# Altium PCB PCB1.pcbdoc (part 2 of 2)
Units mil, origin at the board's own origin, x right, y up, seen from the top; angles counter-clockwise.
Board outline 3543.4 x 3543.1 mil, 4 copper layers (Top Layer, Inner1, Inner2, Bottom Layer), stack 62.5 mil thick; 107 components, 108 nets, 595 pads, 260 vias.
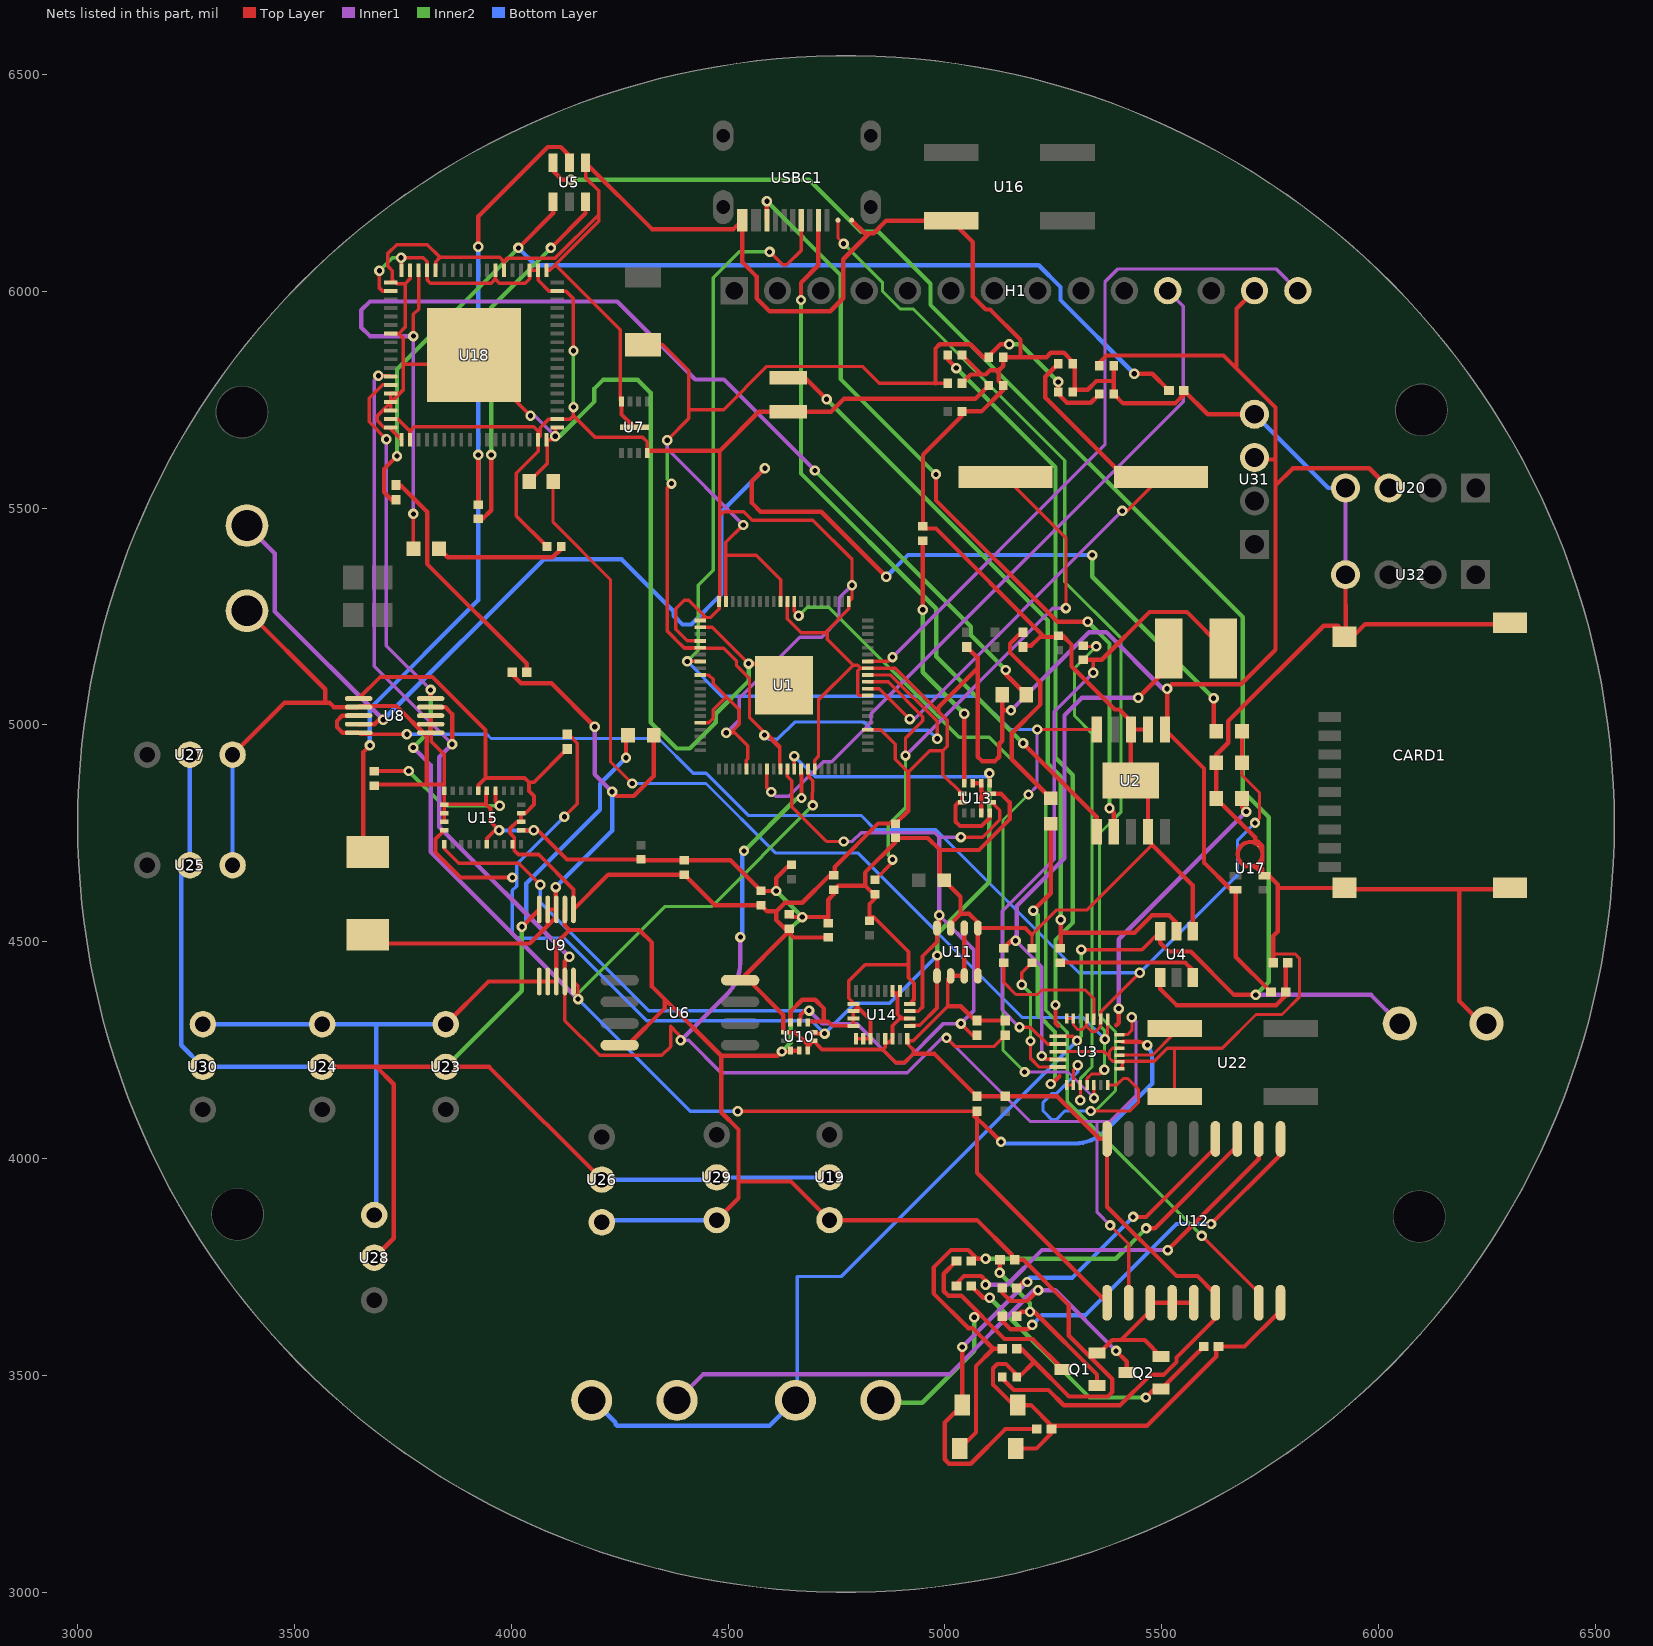
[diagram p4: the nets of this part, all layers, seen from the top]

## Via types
v1: diameter 24, hole 12, Top Layer to Bottom Layer, tented both sides, 260 vias

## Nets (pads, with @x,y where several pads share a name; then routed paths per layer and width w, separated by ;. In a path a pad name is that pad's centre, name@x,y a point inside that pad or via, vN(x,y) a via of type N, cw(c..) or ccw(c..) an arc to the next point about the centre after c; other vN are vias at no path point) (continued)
$1N198: R36.1 U1.11 U10.4 U11.5 U13.11 U14.4 U15.20 | length 2976.1
  Top Layer w7.8: U15.20@3845.1,4725 3845.1,4715 3878.8,4681.3 4016.6,4681.3 v1(4066.6,4631.3) ; U1.11@4636.6,4898.3 4636.6,4881.3 4647,4870.9 4647,4810.9 4726.6,4731.3 v1(4766.6,4731.3) ; v1(5036.6,4741.3) 5086.6,4741.3 5126.6,4781.3 5126.6,4803.2 U13.11@5108.1,4821.7
  Top Layer w8.5: U10.4@4663.7,4314.1 4666.6,4316.9 4666.6,4331.3 4676.6,4341.3 v1(4686.6,4341.3) ; U14.4@4918.7,4340 4919,4339.6 4938.3,4339.6 4948.3,4349.6 4948.3,4466.5 4981.5,4499.6 U11.5@4981.5,4531.6 ; v1(5036.6,4311.3) 5063.5,4284.4 R36.1@5073.8,4284.4
  Top Layer w9.9: U11.5@4981.5,4531.6 4986.6,4536.7 v1(4986.6,4561.3)
  Inner1 w7.8: v1(4766.6,4731.3) 4786.6,4731.3 4806.6,4751.3 4976.6,4751.3 4986.6,4741.3 v1(5036.6,4741.3)
  Inner1 w8.5: v1(4686.6,4341.3) 4716.6,4311.3 4796.6,4311.3 4886.6,4221.3 4906.6,4221.3 4996.6,4311.3 v1(5036.6,4311.3) 5066.6,4341.3 5066.6,4481.3 v1(4986.6,4561.3)
  Inner1 w9.9: v1(4986.6,4561.3) 4986.6,4741.3
  Bottom Layer w7.8: v1(4066.6,4631.3) 4066.6,4591.3 4316.6,4341.3 v1(4686.6,4341.3)
$1N204: C25.1 U15.9 | length 361.3
  Top Layer w8.9: C25.1@3683.7,4893 3684.4,4893.8 v1(3763.2,4893.8) ; U15.9@3963.2,4848 3963.2,4823.8 v1(3973.2,4813.8)
  Inner2 w8.9: v1(3763.2,4893.8) 3843.2,4813.8 v1(3973.2,4813.8)
$1N209: LED2.2 U3.1 | length 669
  Top Layer w10: v1(5203.7,4572) 5243.7,4612 LED2.2@5243.7,4772 ; v1(5243.7,4172) 5246,4172 5263.9,4189.9
  Inner2 w10: v1(5203.7,4572) 5213.7,4562 5213.7,4332 5253.7,4292 5253.7,4182 v1(5243.7,4172)
$1N210: LED2.1 R8.1 | length 491.1
  Top Layer w10: R8.1@5180,5214 5176.7,5214 5150,5187.4 5150,5167.4 5220,5097.4 5220,5047.4 5153.7,4981 5153.7,4921 LED2.1@5243.7,4831
$1N211: C17.1 U3.4 | length 1161.1
  Top Layer w7.1: v1(5312,4134.4) U3.4@5312,4169.7 ; C17.1@5318.7,5183 5320.7,5181.1 v1(5348.7,5181.1)
  Inner2 w7.1: v1(5312,4134.4) 5312,4184.4 5338.7,4211.1 5338.7,4981.1 5298.7,5021.1 5298.7,5131.1 v1(5348.7,5181.1)
$1N212: C17.2 L4.1 U3.26 | length 1460.2
  Top Layer w7.8: v1(5171.7,4303.3) 5196.7,4303.3 5236.7,4263.3 5259.9,4263.3 U3.26@5260.8,4264.2 ; v1(5341.7,5120.4) 5341.7,5150.4
  Top Layer w10: C17.2@5318.7,5150 5319.1,5150.4 5361.7,5150.4 5471.7,5260.4 5557.8,5260.4 L4.1@5641.7,5176.5
  Inner1 w7.8: v1(5171.7,4303.3) 5131.7,4343.3 5131.7,4570.4 5251.7,4690.4 5251.7,5030.4 v1(5341.7,5120.4)
$1N215: U3.12 U22.1 | length 158.8
  Top Layer w7.1: U3.12@5402.5,4238.6 5478.4,4238.6 5529.8,4290 U22.1@5529.8,4300.2
$1N219: C18.1 U3.19 | length 324.4
  Top Layer w7.1: C18.1@5135.5,4452.1 5135.5,4406.6 5163.5,4378.6 5213.5,4378.6 5223.5,4388.6 5323.5,4388.6 5343.5,4368.6 U3.19@5343.5,4321.7
$1N221: R1.1 U3.16 | length 651
  Top Layer w10: 5395.1,4307.6 5400.5,4313 5400.5,4317.4 v1(5400.5,4346) ; R1.1@5684.8,4830.3 5684.8,4810.3 v1(5694.8,4800.3)
  Inner1 w10: v1(5400.5,4346) 5400.5,4506 v1(5694.8,4800.3)
$1N224: C10.1 U3.25 U4.3 U5.3 U21.1 U33.1 | length 5744.7
  Top Layer w7.8: U3.25@5260.8,4281.9 5294.4,4281.9 v1(5304.4,4271.9) ; v1(5314.4,4481.9) 5454.3,4481.9 U4.3@5496.5,4524.2
  Top Layer w10: U5.3@4096.5,6296.5 4096.5,6277.5 4116.5,6257.5 v1(4136.5,6257.5) ; U4.3@5496.5,4524.2 5496.5,4497.5 5516.5,4477.5 5566.5,4477.5 5666.5,4377.5 v1(5716.5,4377.5)
  Inner1 w10: v1(5716.5,4377.5) 5982.7,4377.5 C10.1@6048.7,4311.5
  Inner2 w7.8: v1(5304.4,4271.9) 5314.4,4281.9 v1(5314.4,4481.9)
  Inner2 w10: v1(4136.5,6257.5) 4686.5,6257.5 4806.5,6137.5 4846.5,6137.5 4966.5,6017.5 4966.5,5968.7 5686.5,5248.7 5686.5,4847.5 5746.5,4787.5 5746.5,4407.5 v1(5716.5,4377.5)
  Bottom Layer w7.8: U21.1@4655.1,3442.4 4655.1,3443.7 4659.2,3447.8 4659.2,3727.8 ; 4660.6,3728.1 4760.5,3728.1 v1(5304.4,4271.9)
  Bottom Layer w10: U33.1@4199.4,3431.9 4238.3,3393 ; 4238.23,3392.93 cw(c4231.3,3386) 4241.1,3386 ; 4243.8,3383.7 4595.1,3383.7 U21.1@4655.1,3443.7
$1N225: C19.1 U3.29 | length 309.8
  Top Layer w7.8: v1(5177.2,4401.1) 5177.2,4428.8 C19.1@5200.5,4452.1 ; v1(5197.2,4271.1) 5197.2,4231.1 5217.2,4211.1 U3.29@5259.8,4211.1
  Inner2 w7.8: v1(5177.2,4401.1) 5197.2,4381.1 v1(5197.2,4271.1)
$1N229: C18.2 L4.2 U3.28 | length 1262.7
  Top Layer w7.8: v1(5222.9,4236.6) 5230.8,4228.8 U3.28@5260.8,4228.8
  Top Layer w10: C18.2@5135.5,4485.2 5152.9,4502.6 v1(5162.9,4502.6) ; v1(5445.7,5062.6) 5515.7,5132.6 L4.2@5515.7,5176.5
  Inner1 w7.8: v1(5162.9,4502.6) 5222.9,4442.6 v1(5222.9,4236.6)
  Inner1 w10: v1(5162.9,4502.6) 5162.9,4512.6 5165.7,4515.4 5165.7,4582.6 5275.7,4692.6 5275.7,5022.6 5315.7,5062.6 v1(5445.7,5062.6)
$1N233: U2.7 USBC1.B5 | length 1870.9
  Top Layer w10: v1(4589.3,6207.9) 4589.3,6164.6 USBC1.B5@4589.8,6164.1 ; v1(4979.3,5577.9) 4979.3,5517.9 5259.3,5237.9 v1(5329.3,5237.9) ; v1(5379.3,4807.9) 5389.3,4797.9 U2.7@5389.3,4753.4
  Inner2 w10: v1(4589.3,6207.9) 4759.3,6037.9 4759.3,5797.9 v1(4979.3,5577.9) ; v1(5329.3,5237.9) 5379.3,5187.9 v1(5379.3,4807.9)
$1N234: U2.6 USBC1.A5 | length 1709.8
  Top Layer w10: v1(4667.9,5980) 4667.9,6020 4707.9,6060 USBC1.A5@4707.9,6164.1 ; v1(5180,4957.9) 5350,4787.9 U2.6@5350,4753.4
  Inner2 w10: v1(4667.9,5980) 4667.9,5580 4980,5267.9 4980,5157.9 v1(5180,4957.9)
$1N235: U1.67 U2.5 U3.6 USBC1.A6 | length 3331
  Top Layer w7.1: v1(5343.6,4139.6) U3.6@5343.6,4169.6
  Top Layer w7.8: v1(4405.5,5146.6) U1.67@4435.5,5146.6 ; v1(4595.5,6091) 4625.5,6061 4635.5,6061 4668.5,6094.1 USBC1.A6@4668.5,6164.1 ; v1(5212.5,4989.6) U2.5@5350,4989.6
  Inner1 w7.1: v1(5183.6,4199.6) 5283.6,4199.6 v1(5343.6,4139.6) ; v1(5192.5,4839.6) 5212.5,4859.6 v1(5212.5,4989.6)
  Inner2 w7.1: v1(5183.6,4199.6) 5133.6,4249.6 5133.6,4780.7 v1(5192.5,4839.6)
  Inner2 w7.8: v1(4405.5,5146.6) 4431.2,5172.3 4431.2,5322.3 4465.5,5356.6 4465.5,6031 4525.5,6091 v1(4595.5,6091)
  Bottom Layer w7.8: v1(4405.5,5146.6) 4485.5,5066.6 5073,5066.6 5150,4989.6 v1(5212.5,4989.6)
$1N241: C21.1 U5.6 | length 839.5
  Top Layer w10: C21.1@3923.7,5475 3933.7,5475 3953.7,5495 v1(3953.7,5622.7) ; v1(4091.1,6100.1) 4171.1,6180.1 U5.6@4171.1,6206.2
  Inner2 w10: v1(3953.7,5622.7) 3953.7,5962.7 v1(4091.1,6100.1)
$1N244: C21.2 L3.1 U5.2 | length 1995.2
  Top Layer w10: L3.1@3668.7,4707 3658.7,4717 3658.7,4937.8 v1(3673.7,4952.8) ; C21.2@3923.7,5508 v1(3923.7,5622.8) ; v1(3923.7,6102.8) 3923.7,6172.8 4083.7,6332.8 4113.7,6332.8 4133.7,6312.8 U5.2@4133.7,6296.7
  Bottom Layer w10: v1(3673.7,4952.8) 3673.7,5037.9 3923.7,5287.9 v1(3923.7,5622.8) 3923.7,5630.4 v1(3923.7,6102.8)
$1N254: H1.11 U1.8 | length 1670.9
  Top Layer w7.8: U1.8@4589.3,4898.3 4589.3,4855.3 v1(4599.3,4845.3)
  Inner1 w7.8: v1(4599.3,4845.3) 4609.3,4835.3 4639.3,4835.3 4719.3,4915.3 4739.3,4915.3 4829.3,5005.3 4829.3,5025.3 5549.3,5745.3 5549.3,5965.9 H1.11@5513.7,6001.5
$1N256: R39.1 U1.14 U3.14 U8.5 U9.5 U12.1 U18.31 | length 4802.4
  Top Layer w7.8: U9.5@4143.1,4408.4 4153.8,4397.7 v1(4153.8,4367.7) ; v1(4522.1,4109.4) R39.1@5073.7,4109.4 ; U1.14@4683.8,4898.3 4685.3,4896.8 4685.3,4881.1 4694.8,4871.7 4694.8,4845.5 4694.1,4844.7 4694.1,4826.6 4694.8,4825.9 v1(4694.8,4814.5)
  Top Layer w8.1: v1(3711.9,5658.9) 3671.9,5698.9 3671.9,5753.2 3703,5784.2 U18.31@3721.9,5784.2
  Top Layer w10: v1(3813.8,5080.8) U8.5@3813.9,5060.9 ; 5067.42,4097.81 cw(c4448.4,3393.2) 5073.54,4092.38 ; 5067.4,4097.9 5071.1,4097.9 ; 5073.61,4092.36 cw(c4448.4,3393.1) v1@5128.8,4038.78 ; R39.1@5073.7,4109.4 5073.7,4092.2 5073.7,3967.5 U12.1@5373.7,3667.5 ; U3.14@5409.8,4269.2 5445.2,4269.2 ; 5445.2,4269.3 cw(c5445.2,4239.6) v1@5466.2,4260.6
  Inner1 w8.1: v1(3711.9,5658.9) 3711.9,5182.7 v1(3813.8,5080.8)
  Inner1 w10: v1(3773.8,4947.7) 3813.8,4907.7 3813.8,4707.7 v1(4153.8,4367.7)
  Inner2 w7.8: v1(4153.8,4367.7) 4153.8,4381.3 4353.8,4581.3 4461.6,4581.3 v1(4694.8,4814.5)
  Inner2 w10: v1(3773.8,4947.7) 3813.8,4987.7 v1(3813.8,5080.8)
  Bottom Layer w7.8: v1(4153.8,4367.7) 4412.1,4109.4 v1(4522.1,4109.4)
  Bottom Layer w10: v1@5129.2,4035 5298.8,4035 ccw(c5298.8,4135) 5369.51,4064.29 5478.1,4172.9 5478.1,4227.5 ; v1@5466.84,4261.54 cw(c5420.5,4227.5) 5478,4227.5
  other v1: 5129.1,4038.4 5466.7,4261.7
$1N259: C22.1 U13.4 | length 598.7
  Top Layer w9.9: v1(4948.7,5265.9) C22.1@4948.7,5425 ; U13.4@5044.2,4865.9 v1(5044.2,5025.9)
  Inner2 w9.9: v1(4948.7,5265.9) 4948.7,5121.4 v1(5044.2,5025.9)
$1N260: C20.1 U4.6 | length 329.6
  Top Layer w10: C20.1@5265.6,4452.1 5553.7,4452.1 5571.3,4434.5 U4.6@5571.3,4417.9
$1N262: R2.2 R31.1 U4.4 | length 418.2
  Top Layer w10: U4.4@5496.5,4417.9 5496.5,4391.2 5533.8,4353.9 5763.8,4353.9 5785.8,4375.9 R2.2@5785.8,4383.9 5785.8,4446.6 R31.1@5790.7,4451.5
$1N267: R5.2 R32.1 U5.4 | length 2519.5
  Top Layer w10: R5.2@3733.7,5519.5 3723.7,5519.5 3706.3,5536.8 3706.3,5590.1 v1(3736.3,5620.1) ; v1(4016.3,6100.1) 4096.3,6180.1 U5.4@4096.3,6206.2 ; v1(5436.3,5810.1) 5478,5810.1 R32.1@5516.7,5771.5
  Inner2 w10: v1(3736.3,5620.1) 3736.3,5820.1 v1(4016.3,6100.1)
  Bottom Layer w10: v1(4016.3,6100.1) 4056.3,6060.1 5216.3,6060.1 5266.3,6010.1 5266.3,5980.1 v1(5436.3,5810.1)
$1N277: C20.2 L2.1 U4.2 | length 1909.2
  Top Layer w10: L2.1@4638.7,5800.9 4677,5800.9 v1(4727,5750.9) ; C20.2@5265.6,4485.2 5267,4486.6 v1(5267,4550.9) ; 5267,4520.9 5437,4520.9 5477,4560.9 5517,4560.9 5533.9,4543.9 U4.2@5533.9,4524.2
  Inner2 w10: v1(4727,5750.9) 5237,5240.9 5237,4910.9 5267,4880.9 v1(5267,4550.9)
$1N278: H1.14 U1.34 | length 1606.9
  Top Layer w7.8: U1.34@4821.9,5146.6 4868.9,5146.6 v1(4878.9,5156.6)
  Inner1 w7.8: v1(4878.9,5156.6) 5368.9,5646.6 5368.9,6021.5 5398.9,6051.5 5763.7,6051.5 H1.14@5813.7,6001.5
$1N293: C2.1 U1.30 X1.2 | length 1369.6
  Top Layer w7.8: U1.30@4821.9,5083.6 4848.9,5083.6 v1(4918.9,5013.6) ; v1(5408.9,5493.6) 5420.1,5493.6 X1.2@5498,5571.5
  Top Layer w10: C2.1@5261.1,5833.1 5231.1,5803.1 5231.1,5755.1 5414.7,5571.5 X1.2@5498,5571.5
  Inner1 w7.8: v1(4918.9,5013.6) 4928.9,5013.6 v1(5408.9,5493.6)
$1N294: C3.1 U1.31 X1.1 | length 1461.2
  Top Layer w7.8: U1.31@4821.9,5099.4 4868.9,5099.4 4948.9,5019.4 4948.9,5009.4 4908.9,4969.4 v1(4908.9,4929.4) ; C3.1@4838.7,4643 4878.9,4683.2 v1(4878.9,4689.4) ; X1.1@5139.4,5571.5 5278.9,5432 v1(5278.9,5269.4)
  Inner1 w7.8: v1(4908.9,4929.4) 5248.9,5269.4 v1(5278.9,5269.4)
  Inner2 w7.8: v1(4878.9,4689.4) 4868.9,4699.4 4868.9,4769.4 4908.9,4809.4 v1(4908.9,4929.4)
$1N305: L3.2 R4.1 R7.2 U9.8 U9.9 | length 1523.7
  Top Layer w10: L3.2@3668.7,4516 3688.7,4496 4042.4,4496 4084,4537.7 U9.9@4084,4574.6 U9.8@4103.7,4574.6 ; R4.1@4001.7,5121.5 4001.7,5116.7 4022.4,5096 4092.4,5096 v1(4192.4,4996) ; 4062.4,4516 4102.4,4556 v1(4102.4,4626) ; v1(4232.4,4846) 4242.4,4836 4282.4,4836 4328.4,4882 R7.2@4328.4,4976.5
  Inner1 w10: v1(4192.4,4996) 4192.4,4886 v1(4232.4,4846)
  Bottom Layer w10: v1(4102.4,4626) 4232.4,4756 v1(4232.4,4846)
$1N307: R3.1 R12.1 U3.18 U3.20 U3.22 U3.23 U8.8 U8.10 | length 3149.7
  Top Layer w7.1: U8.10@3647.7,4982.1 3651.2,4978.6 v1(3759.2,4978.6) ; U3.23@5280.5,4323.3 U3.22@5296.2,4323.3 5296.2,4307.9 5306.2,4297.9 5316.2,4297.9 5326.2,4307.9 5326.2,4321.8 U3.20@5327.7,4323.3 5327.7,4303.3 5337.7,4293.3 5347.7,4293.3 5357.7,4303.3 5357.7,4320.8 U3.18@5359.2,4322.3 5359.2,4338.6 v1(5449.2,4428.6) ; R12.1@5684.8,4913 5684.8,4884.2 5724.8,4844.2 5724.8,4784.2 v1(5714.8,4774.2)
  Top Layer w10: U8.10@3647.7,4982.1 3610.8,4982.1 3597.9,4995 3597.9,5009.2 3610.2,5021.5 U8.8@3647.7,5021.5 ; R12.1@5684.8,4913 R3.1@5684.8,4985.7
  Bottom Layer w7.1: v1(3759.2,4978.6) 3943,4978.6 3953,4968.6 4339.2,4968.6 4419.2,4888.6 4449.2,4888.6 4546.2,4791.6 4806.2,4791.6 4839.2,4758.6 4979.2,4758.6 5309.2,4428.6 v1(5449.2,4428.6) 5674.8,4654.2 5674.8,4734.2 v1(5714.8,4774.2)
$1N308: CN1.1 R3.2 U8.9 | length 3494
  Top Layer w10: U8.9@3647.7,5001.8 3684.6,5001.8 3694.6,5011.8 v1(3704.6,5011.8) ; v1(4584.6,5591.8) 4554.6,5561.8 4554.6,5511.8 4574.6,5491.8 4714.6,5491.8 v1(4864.6,5341.8) ; v1(5619.4,5061.8) 5619.4,4991.8 R3.2@5625.5,4985.7
  Inner1 w10: CN1.1@3390.2,5459.9 3454.6,5395.5 3454.6,5261.8 v1(3704.6,5011.8)
  Inner2 w10: v1(5339.4,5391.8) 5339.4,5341.8 v1(5619.4,5061.8)
  Bottom Layer w10: v1(3704.6,5011.8) 4074.6,5381.8 4254.6,5381.8 4374.6,5261.8 4374.6,5251.8 4394.6,5231.8 4414.6,5231.8 4484.6,5301.8 4484.6,5491.8 v1(4584.6,5591.8) ; v1(4864.6,5341.8) 4914.6,5391.8 v1(5339.4,5391.8)
$1N310: R4.2 R5.1 | length 563
  Top Layer w10: R5.1@3733.7,5553.5 3735.7,5551.5 3745.7,5551.5 3805.7,5491.5 3805.7,5371.5 4035.7,5141.5 R4.2@4035.7,5121.5
$1N315: R7.1 U9.10 U19.2 U23.2 U24.2 U25.2 U26.2 U27.2 U28.2 U29.2 U30.2 | length 3774.6
  Top Layer w10: U24.2@3563.7,4211.5 U23.2@3848.7,4211.5 3948.7,4211.5 U26.2@4208.7,3951.5 ; U28.2@3683.7,3771.5 3728.7,3816.5 3728.7,4171.5 3688.7,4211.5 ; v1(4024.3,4534.6) U9.10@4064.3,4574.6 ; v1(4264.3,4924.6) 4264.3,4971.8 R7.1@4269,4976.5
  Inner2 w10: U23.2@3848.7,4211.5 4024.3,4387.1 v1(4024.3,4534.6)
  Bottom Layer w10: U27.2@3258.7,4931.5 U25.2@3258.7,4676.5 3238.7,4656.5 3238.7,4261.5 U30.2@3288.7,4211.5 U24.2@3563.7,4211.5 ; v1(4024.3,4534.6) 4034.3,4544.6 4034.3,4634.6 4204.3,4804.6 4204.3,4864.6 v1(4264.3,4924.6) ; U26.2@4208.7,3951.5 4468.7,3951.5 U29.2@4473.7,3956.5 U19.2@4733.7,3956.5
$1N316: C6.1 U3.24 | length 1685.1
  Top Layer w10: C6.1@5006.1,5853 5006.1,5843 v1(5026.1,5823) ; v1(5254.9,4354.2) U3.24@5254.9,4316.4 5254.9,4312.4 5260.8,4306.5
  Inner2 w10: v1(5026.1,5823) 5254.9,5594.2 5254.9,4924.2 5294.9,4884.2 5294.9,4544.2 5254.9,4504.2 v1(5254.9,4354.2)
$1N322: C8.2 R10.1 U18.16 | length 2750.3
  Top Layer w8.1: R10.1@3774,5406.5 v1(3774,5486.7) ; v1(3774,5896.7) 3774,5946.7 3786.1,5958.8 U18.16@3786.1,6048.6
  Top Layer w10: v1(5140.1,5126.7) 5140.1,5116.7 C8.2@5187.3,5069.5
  Inner1 w8.1: v1(3774,5486.7) v1(3774,5896.7)
  Inner1 w10: v1(3774,5896.7) 3674,5896.7 3654,5916.7 3654,5956.7 3674,5976.7 4244,5976.7 4424,5796.7 4490.1,5796.7 v1(4700.1,5586.7)
  Inner2 w10: v1(4700.1,5586.7) 5060.1,5226.7 5060.1,5206.7 v1(5140.1,5126.7)
$1N323: C9.2 R10.2 | length 303.4
  Top Layer w10: R10.2@3833.4,5406.5 3853.4,5386.5 4095.2,5386.5 4115.2,5406.5 C9.2@4115.2,5411.5
$1N330: C7.1 U3.5 U3.17 | length 2356
  Top Layer w7.1: C7.1@4096.3,5561.5 4096.3,5467.6 4228.8,5335.1 4228.8,4915.1 v1(4278.8,4865.1) ; U3.5@5327.7,4169.7 5327.7,4185.1 5337.7,4195.1 5357.7,4195.1 v1(5367.7,4205.1) ; v1(5368.8,4275.1) 5375,4281.3 U3.17@5375,4321.3
  Inner2 w7.1: v1(5367.7,4205.1) 5367.7,4295.1 5358.8,4304 5358.8,4304.6 5359.3,4304.6 5368.8,4295.1 v1(5368.8,4275.1)
  Bottom Layer w7.1: v1(4278.8,4865.1) 4448.8,4865.1 4608.8,4705.1 4798.8,4705.1 5178.8,4325.1 5318.8,4325.1 v1(5368.8,4275.1)
$1N333: R37.1 U1.12 U10.2 U11.4 U13.1 U14.2 U15.19 | length 3188.6
  Top Layer w7.8: v1(4122.3,4788.3) 4152.3,4818.3 4152.3,4958.3 4132.1,4978.5 R37.1@4128.7,4978.5 ; U1.12@4652.3,4898.3 v1(4652.3,4928.3) ; v1(5102.3,4888.3) 5102.3,4866.9 U13.1@5103.2,4865.9
  Top Layer w8.5: U10.2@4696.5,4291.1 4699.3,4288.3 v1(4722.3,4288.3) ; U14.2@4918.7,4306.1 4920,4307.4 4941.5,4307.4 4981.5,4347.4 U11.4@4981.5,4427.4
  Top Layer w8.9: U15.19@3845.1,4757 3825.1,4737 3825.1,4705.5 3882.3,4648.3 v1(4002.3,4648.3)
  Top Layer w9.9: U11.4@4981.5,4421.4 4981.5,4427.4 4982.3,4428.3 v1(4982.3,4468.3)
  Inner2 w9.9: v1(4982.3,4468.3) 4982.3,4518.3 5102.3,4638.3 v1(5102.3,4888.3)
  Bottom Layer w7.8: v1(4122.3,4788.3) 4012.3,4678.3 4012.3,4628.3 4002.3,4618.3 4002.3,4518.3 4012.3,4508.3 4122.3,4508.3 4312.3,4318.3 4692.3,4318.3 v1(4722.3,4288.3) ; v1(4652.3,4928.3) 4700.4,4880.2 5094.3,4880.2 v1(5102.3,4888.3)
  Bottom Layer w8.5: v1(4722.3,4288.3) 4732.3,4298.3 4792.3,4358.3 4872.3,4358.3 v1(4982.3,4468.3)
  Bottom Layer w8.9: v1(4002.3,4648.3) 4012.3,4638.3
$1N335: C1.2 C2.2 C3.2 C4.2 C5.2 C6.2 C7.2 C10.2 C11.2 C12.2 C13.2 C14.2 C16.2 C19.2 C22.2 C23.2 C24.2 C25.2 C26.2 C27.2 C28.2 C29.2 C30.2 C31.2 C32.2 C33.2 CARD1.10 CARD1.11 CARD1.12 CARD1.13 CN1.2 D1.2 D2.2 LED1.1 Q1.2 Q2.2 R1.2 R8.2 R12.2 R14.2 R15.2 R19.2 R20.2 R31.2 R32.2 U1.62 U1.81 U2.2 U2.3 U2.9 U2.11 U3.10 U3.11 U3.13 U3.27 U4.1 U5.1 U6.4 U7.4 U7.9 U8.1 U8.2 U8.3 U8.7 U9.1 U9.2 U9.3 U9.7 U10.3 U10.5 U10.8 U10.9 U11.1 U11.6 U11.8 U12.3 U12.4 U12.5 U12.9 U13.2 U13.3 U13.9 U13.12 U14.5 U14.14 U14.15 U14.16 U14.17 U14.18 U14.19 U14.20 U15.2 U15.10 U15.15 U15.16 U15.17 U15.18 U15.25 U16.3 U17.4 U17.5 U18.1 U18.6 U18.14 U18.17 U18.19 U18.25 U18.32 U18.33 U18.34 U18.36 U18.37 U18.54 U18.55 U18.73 U19.3 U20.4 U22.3 U23.3 U24.3 U25.3 U26.3 U27.3 U28.3 U29.3 U30.3 U31.4 U32.4 USBC1.A1B12 USBC1.B1A12 | length 24588.2
  Top Layer w7.1: U3.27@5260.8,4246.5 5367.2,4246.5 5379.3,4234.4 ; U3.10@5402.5,4207.1 5409.3,4213.9 U3.11@5409.3,4224.4 ; U3.13@5402.5,4254.4 5386.4,4254.4 5379.3,4247.3 5379.3,4234.4 ; U22.3@5529.8,4142.8 5529.3,4143.3 5529.3,4254.4 ; 5757.2,4472.2 5807.2,4472.2 5817.2,4462.2 5817.2,4372.2 5777.2,4332.2 5717.2,4332.2 5639.3,4254.4 5529.3,4254.4 ; 5379.3,4234.4 5379.3,4231.4 5386.4,4224.4 U3.11@5409.3,4224.4 ; U3.11@5409.3,4224.4 5482.7,4224.4 5512.7,4254.4 5529.3,4254.4
  Top Layer w7.8: U1.62@4435.5,5225.4 4463.2,5225.4 v1(4547.1,5141.5) ; C19.2@5200.5,4485.2 5200.5,4515.8 5258.1,4573.4 5328.1,4573.4 5478.1,4723.4
  Top Layer w8.1: U18.34@3721.9,5725.2 U18.33@3721.9,5744.1 ; U18.33@3721.9,5744.8 U18.32@3721.9,5764.5 3742.4,5764.5 ; U18.25@3721.9,5902.3 3740.2,5902.3 ; U18.19@3721.9,6020.4 3725.5,6024 3725.5,6027.6 ; U18.37@3746.7,5657.6 3721.9,5682.4 U18.36@3721.9,5685.8 3706.7,5685.8 3690.2,5702.3 3690.2,5712.3 U18.33@3721.9,5744.1 ; U18.17@3766.4,6048.6 3766.4,6028.6 3755.5,6017.6 ; U18.14@3825.5,6048.6 3825.5,6068.6 3835.5,6078.6 ; U18.6@3983,6048.6 3983,6068.6 ; C7.2@4041.1,5561.5 4083.2,5603.6 U18.54@4083.2,5657.6 ; v1(4044.1,5713.1) 3914.1,5843.1 U18.73@3914.1,5853.1 3893.3,5832.3 3750.2,5832.3 ; U18.54@4081.4,5657.6 U18.54@4083.2,5657.6 ; U18.1@4081.4,6048.6 4088.1,6048.6 4101.1,6061.6 ; U18.55@4106.2,5685.8 4101.4,5681 v1(4101.4,5665.8) 4093.2,5657.6 U18.54@4083.2,5657.6 ; U5.1@4171.1,6296.7 4171.1,6261.6 4201.1,6231.6 4201.1,6176.7 ; U7.4@4254.2,5745.8 4251.1,5748.9 4251.1,5911.6 4101.1,6061.6 ; U18.33@3721.9,5744.1 3742.4,5764.5 ; 3725.5,6027.6 3725.5,6047.6 3715.5,6057.6 3715.5,6087.6 3735.5,6107.6 3806.4,6107.6 3835.5,6078.6 ; 3725.5,6027.6 3735.5,6017.6 3755.5,6017.6 ; 3740.2,5902.3 3755.5,5917.6 3755.5,6017.6 ; 3740.2,5902.3 3750.2,5892.3 3750.2,5832.3 ; 3742.4,5764.5 3750.2,5772.3 3750.2,5832.3 ; 3835.5,6078.6 3973,6078.6 3983,6068.6 ; 3983,6068.6 3991.1,6076.7 4101.1,6076.7 4201.1,6176.7 ; 4101.1,6061.6 4201.1,6161.6 4201.1,6176.7
  Top Layer w8.5: U10.3@4683.4,4314.1 4685.4,4316.1 4720.7,4316.1 4730.7,4316.1 4740.7,4306.1 U14.17@4788.7,4306.1 U14.16@4788.7,4323 U14.15@4788.7,4340 4798.3,4349.6 4828.3,4319.6 U14.20@4828.3,4276.4 U14.19@4811.4,4276.4 U14.18@4794.4,4276.4 ; U14.14@4788.7,4356.9 4788.3,4357.3 4788.3,4359.6 4778.3,4369.6 4778.3,4409.6 4815.8,4447 4915.8,4447 ; C23.2@4825.8,4557 4835.8,4557 4915.8,4477 4915.8,4447 ; U14.5@4918.7,4356.9 4928.7,4366.9 4928.7,4404.1 4915.8,4417 4915.8,4447
  Top Layer w8.9: C25.2@3683.7,4859.9 3686,4862.3 3805.1,4862.3 3845.1,4862.3 3845.1,4932.3 3815.1,4962.3 3815.1,4980.9 U8.1@3813.9,4982.1 ; U15.18@3845.1,4776.6 U15.17@3845.1,4796.3 U15.16@3845.1,4816 ; U15.15@3845.1,4848 U15.16@3845.1,4816 ; U15.25@3943.5,4725 3943.5,4738.8 3961.7,4757 v1(3971.7,4757) 3951.7,4777 3951.7,4807 3941.7,4817 ; U15.10@3943.5,4848 3941.7,4846.2 3941.7,4817 ; U15.2@4022.3,4757 4061.7,4757 4128.7,4689.9 C5.2@4298.7,4689.9 ; U15.16@3845.1,4816 3846.1,4817 3941.7,4817
  Top Layer w9.9: U7.4@4254.2,5745.8 4254.2,5716 U7.9@4283.7,5686.5 ; U29.3@4473.7,3858.1 4524,3908.4 4524,3947 4524,4067 4484,4107 4484,4237 ; v1(4624,4247) 4642.1,4247 U10.8@4644,4248.9 U10.9@4663.7,4248.9 ; U10.5@4644,4314.1 4644,4339.4 4670.7,4366.1 4700.7,4366.1 4720.7,4346.1 4720.7,4316.1 ; 4988.2,4711.5 5078.2,4711.5 5149.1,4782.3 5149.1,4821.5 5129.1,4841.5 U13.12@5109.1,4841.5 ; U13.3@5063.9,4865.9 U13.2@5083.5,4865.9 5083.5,4847 5089.1,4841.5 ; U13.9@5083.5,4797 5083.5,4835.9 5089.1,4841.5 ; U13.12@5108.1,4841.3 U13.12@5109.1,4841.5 ; 5089.1,4841.5 U13.12@5109.1,4841.5
  Top Layer w10: U27.3@3357.1,4931.5 3476.8,5051.2 3570.8,5051.2 ; CN1.2@3390.2,5263.1 3570.8,5082.4 3570.8,5051.2 ; 3805.1,4862.3 3805.1,4973.8 3735.1,5043.8 3650.3,5043.8 U8.7@3647.7,5041.2 3590.8,5041.2 3580.8,5051.2 3570.8,5051.2 ; U8.1@3813.9,4982.1 U8.2@3813.9,5001.8 U8.3@3813.9,5021.5 ; U23.3@3848.7,4309.9 3947.2,4408.4 U9.1@4064.3,4408.4 U9.2@4084,4408.4 U9.3@4103.7,4408.4 4103.7,4496.7 4134,4527 ; U9.7@4123.4,4574.6 4123.4,4537.6 4134,4527 ; U5.1@4171.1,6296.7 4324.3,6143.5 4512.1,6143.5 USBC1.B1A12@4532.7,6164.1 4532.7,6066.9 4565.5,6034.1 4565.5,5984.1 4595.5,5954.1 4735.5,5954.1 4765.5,5984.1 4765.5,6074.1 4825.5,6134.1 ; U6.4@4249.7,4261.5 4268.5,4261.5 4354,4347 4354,4367 ; C5.2@4298.7,4689.9 4300.6,4688 C29.2@4398.7,4688 4505.3,4688 C27.2@4575.8,4617.6 4576.4,4617 v1(4610.8,4617) 4610.8,4647 4641.4,4677.6 C24.2@4645.8,4677.6 ; 4524,3947 4644.8,3947 U19.3@4733.7,3858.1 5073.7,3858.1 5153.7,3778.1 5153.7,3773.5 R14.2@5160.7,3766.5 5180.7,3766.5 5285.7,3661.5 5285.7,3591.5 5385.7,3491.5 5385.7,3461.5 5375.7,3451.5 5285.7,3451.5 5205.7,3531.5 ; v1(4547.1,5141.5) 4578.7,5141.5 U1.81@4628.7,5091.5 ; v1(4624,4247) 4614,4237 4484,4237 4354,4367 ; C32.2@4640.7,4563.1 4646.8,4557 v1(4670.8,4557) 4730.8,4557 ; C26.2@4730.8,4543.1 4730.8,4557 ; USBC1.A1B12@4784.7,6164.1 4814.7,6134.1 4825.5,6134.1 ; C23.2@4825.8,4548.1 4825.8,4557 4825.8,4587 4838.7,4599.9 4838.7,4609.9 4835.4,4609.9 4815.8,4629.5 ; C22.2@4948.7,5458 C22.2@4949.1,5453 ; U11.6@5012.9,4531.6 5012.9,4541.3 5035.9,4564.3 ; C1.2@5039.1,5723 5039.1,5713 4949.1,5623 C22.2@4949.1,5453 ; C14.2@5039.1,5788 5059.3,5808.1 5084.1,5808.1 ; C6.2@5039.1,5853 5084.1,5808.1 ; C1.2@5039.3,5723.1 5084.1,5723.1 5134.1,5773.1 5134.1,5783.1 5124.1,5793.1 5124.1,5818.1 ; U11.1@5075.9,4421.4 U11.8@5075.9,4531.6 ; D2.2@5163.1,3331.5 5210.7,3331.5 5245.7,3366.5 R19.2@5245.7,3376.5 R19.2@5245.7,3383.8 ; C16.2@5165.2,3496.5 C16.2@5170.7,3496.5 ; R15.2@5165.7,3561.5 5175.7,3561.5 5205.7,3531.5 ; R8.2@5180,5179.9 5183.1,5183 5199.1,5183 5219.1,5203 5229.1,5203 ; 5200.5,4515.8 5184.8,4531.6 U11.8@5075.9,4531.6 ; C13.2@5294.1,5768 C13.2@5299.1,5773.1 ; Q1.2@5350.7,3551.4 5355.7,3551.5 5385.7,3581.5 5405.7,3581.5 ; C28.2@5389.1,5828.2 5389.1,5793.1 ; U2.9@5468.1,4753.4 5468.1,4832.1 U2.11@5428.7,4871.5 U2.3@5428.7,4989.6 ; U2.2@5468.1,4989.6 U2.3@5428.7,4989.6 ; 5478.1,4723.4 5571.3,4630.1 U4.1@5571.3,4524.2 ; Q2.2@5498.1,3543.9 5460.5,3581.5 5405.7,3581.5 ; U12.5@5573.7,3667.5 U12.4@5523.7,3667.5 U12.3@5473.7,3667.5 5473.7,3649.5 5405.7,3581.5 ; 5694.48,4674.43 cw(c5703.7,4701.5) 5696.11,4729.07 cw(c5703.7,4701.5) 5718.64,4725.89 cw(c5703.7,4701.5) 5732.3,4701.5 ; 5711.29,4673.91 cw(c5705.3,4651.7) 5722.42,4667.06 ; 5711.29,4673.93 ccw(c5703.7,4701.5) 5732.3,4701.5 ; U31.4@5713.7,5716.5 5605.7,5716.5 R32.2@5550.7,5771.5 5550.7,5761.5 5530.7,5741.5 5410.8,5741.5 5389.1,5763.1 5389.1,5793.1 ; 5718.7,4725.9 5715.5,4730.3 ; 5722.4,4667 5729.5,4667 ; 5732.3,4667 5732.3,4657 U17.4@5737.2,4652.2 5747.2,4652.2 5767.2,4632.2 5767.2,4624.1 ; 5732.3,4680.2 5732.3,4701.5 ; R31.2@5756.7,4451.5 5757.2,4452 5757.2,4472.2 5757.2,4513.5 5767.2,4523.5 5767.2,4624.1 ; U12.9@5773.7,3667.5 5770.7,3664.6 5770.7,3646.5 5690.7,3566.5 R20.2@5630.7,3566.5 5625.7,3561.5 5625.7,3543.8 5465.7,3383.8 R19.2@5245.7,3383.8 ; 5923.7,5278.4 U32.4@5923.7,5346.5 ; 5923.9,5276.3 5923.9,5232.7 ccw(c5958.9,5232.7) CARD1.13@5934.15,5207.95 ; CARD1.13@5930.4,5204.2 5905.7,5228.9 5873.2,5228.9 5653.2,5008.9 5653.2,4958.9 5625.5,4931.3 R12.2@5625.5,4913 R1.2@5625.5,4830.3 5715.5,4740.3 5715.5,4730.3 ; CARD1.10@5934.5,4622.2 5935.7,4621 6185.7,4621 ; CARD1.13@5939.5,5202.7 5968.8,5232 CARD1.12@6317.7,5232 ; CARD1.10@5942,4624.1 5767.2,4624.1 ; C10.2@6242.5,4306.5 6185.7,4363.4 6185.7,4621 ; C10.2@6248.7,4311.5 C10.2@6253.2,4315.9 ; CARD1.11@6317.7,4621 6185.7,4621 ; 4134,4527 4295.1,4527 4324,4498.1 4324,4397 4354,4367 ; 4730.8,4557 4730.8,4597 4743.7,4609.9 4743.7,4619.9 4753.3,4629.5 4815.8,4629.5 ; 4815.8,4629.5 4815.8,4659.5 4885.8,4729.5 4885.8,4739.5 4960.2,4739.5 4988.2,4711.5 4988.2,4651.5 LED1.1@4998.2,4641.5 5035.9,4603.8 5035.9,4564.3 ; 4825.5,6134.1 4835.5,6134.1 4864.2,6162.7 5014.8,6162.7 5064.1,6113.4 5064.1,5988.1 5094.1,5958.1 5104.1,5958.1 5174.1,5888.1 5174.1,5848.1 ; C22.2@4949.1,5453 4979.1,5453 5229.1,5203 ; 5035.9,4564.3 5055.9,4564.3 5075.9,4544.3 U11.8@5075.9,4531.6 ; 5084.1,5808.1 5094.1,5808.1 5104.1,5818.1 5124.1,5818.1 ; 5124.1,5818.1 5134.1,5828.1 5134.1,5848.1 5174.1,5848.1 ; C16.2@5170.7,3496.5 5205.7,3531.5 ; C16.2@5170.7,3496.5 5140.7,3526.5 5120.7,3526.5 5110.7,3516.5 5110.7,3478.8 5158.1,3431.5 D1.2@5168.1,3431.5 5198.1,3431.5 R19.2@5245.7,3383.8 ; 5174.1,5848.1 5234.1,5848.1 5244.1,5858.1 5274.1,5858.1 5294.1,5838.1 5294.1,5833.1 5299.1,5828.1 C13.2@5299.1,5773.1 ; 5229.1,5203 5258.9,5203 C4.2@5261.6,5205.6 5271.6,5205.6 5291.6,5185.6 5291.6,5135.6 5391.6,5035.6 5401.6,5035.6 5428.7,5008.5 U2.3@5428.7,4989.6 ; C13.2@5299.1,5773.1 5329.1,5773.1 5349.1,5793.1 5389.1,5793.1 ; 5715.5,4730.3 5722.3,4730.3 5732.3,4720.3 5732.3,4701.5
  Inner1 w8.1: v1(4044.1,5713.1) 4054.1,5713.1 4081.4,5685.8 v1(4101.4,5665.8)
  Inner1 w10: U32.4@5923.7,5346.5 U20.4@5923.7,5546.5
  Inner2 w9.9: v1(4624,4247) 4644,4267 4644,4530.3 v1(4670.8,4557)
  Inner2 w10: v1(4101.4,5665.8) 4111.4,5665.8 4191.4,5745.8 4191.4,5775.8 4211.4,5795.8 4291.4,5795.8 4321.4,5765.8 4321.4,5005.8 4381.4,4945.8 4411.4,4945.8 4471.4,5005.8 4471.4,5025.8 4547.1,5101.5 v1(4547.1,5141.5) ; v1(4610.8,4617) v1(4670.8,4557)
  Bottom Layer w8.9: v1(3971.7,4757) v1(4051.7,4757)
  Bottom Layer w10: U30.3@3288.7,4309.9 U24.3@3563.7,4309.9 3688.7,4309.9 ; U25.3@3357.1,4676.5 U27.3@3357.1,4931.5 ; U28.3@3683.7,3869.9 3688.7,3874.9 3688.7,4309.9 ; U23.3@3848.7,4309.9 3688.7,4309.9 ; U26.3@4208.7,3853.1 4213.7,3858.1 U29.3@4473.7,3858.1 ; U31.4@5713.7,5716.5 5883.7,5546.5 U20.4@5923.7,5546.5
$1N338: C8.1 C9.1 C16.1 C26.1 C27.1 C28.1 C29.1 C30.1 C31.1 C32.1 C33.1 H1.13 L2.2 R2.1 R6.2 R17.2 R36.2 R37.2 R38.2 R39.2 U1.5 U1.15 U1.24 U1.29 U1.33 U1.41 U1.50 U1.60 U1.61 U1.64 U1.69 U1.76 U2.1 U6.8 U7.8 U8.6 U9.6 U10.1 U10.6 U10.10 U11.2 U11.3 U11.7 U12.6 U12.18 U13.5 U13.6 U13.10 U14.1 U14.3 U14.7 U14.8 U14.22 U14.23 U15.3 U15.4 U15.11 U15.28 U17.1 U18.2 U18.3 U18.7 U18.15 U18.18 U18.20 U18.35 U18.38 U18.53 U18.56 U18.71 U20.3 U31.3 | length 15736.1
  Top Layer w7.8: U1.76@4435.5,5004.9 4455.3,5004.9 4465.5,5015.1 4465.5,5035.1 4495.5,5065.1 ; U1.69@4435.5,5115.1 4455.5,5115.1 4465.5,5105.1 4465.5,5095.1 4525.5,5035.1 4525.5,5002.1 v1@4505.5,4982.1 ; U1.64@4435.5,5193.8 4405.5,5193.8 4379.1,5220.2 4379.1,5267.7 4399.1,5287.7 4409.1,5287.7 4449.1,5247.7 ; U1.61@4435.5,5241.1 4442.1,5247.7 4459.1,5247.7 4479.1,5267.7 U1.60@4479.1,5284.7 4480.4,5286 4480.4,5632.1 ; 4480.4,5482.1 4490.4,5492.1 4535.5,5492.1 4555.5,5472.1 4695.5,5472.1 4785.5,5382.1 v1(4785.5,5322.1) 4785.5,5291.9 U1.41@4778.3,5284.7 4778.3,5267.7 4723.6,5213 4668.3,5213 4636.6,5244.7 U1.50@4636.6,5284.7 ; v1(4495.5,4982.1) v1@4505.5,4982.1 ; U1.5@4542.1,4898.3 4542.1,4918.7 4545.5,4922.1 4545.5,4952.1 4515.5,4982.1 v1@4505.5,4982.1 ; U1.15@4699.6,4898.3 4699.6,4919 4708.3,4927.7 4708.3,5057.7 4788.3,5137.7 ; 4728.3,5217.7 4728.3,5197.7 4788.3,5137.7 ; U1.33@4815.2,5130.9 4885.2,5130.9 5005.2,5010.9 5005.2,4950.9 4995.2,4940.9 ; U1.24@4821.9,4989.1 4851.9,4989.1 4885.2,4955.9 4885.2,4920.9 4915.2,4890.9 4965.2,4940.9 4995.2,4940.9 ; U1.29@4821.9,5067.9 4801.9,5067.9 4798.9,5070.9 4798.9,5124.6 4805.2,5130.9 ; U1.33@4821.9,5130.9 4805.2,5130.9 ; U13.5@5039.3,4841.3 4995.2,4885.4 4995.2,4940.9 ; 4788.3,5137.7 4798.3,5137.7 4805.2,5130.9
  Top Layer w8.1: v1(3695.8,6047.6) 3695.8,6007.6 3702.7,6000.7 U18.20@3721.9,6000.7 ; U18.35@3721.9,5705.5 3738.2,5705.5 3766.2,5677.5 ; v1(3745.8,6077.6) v1@3745.8,6067.6 ; U18.18@3746.7,6048.6 3745.8,6049.5 v1@3745.8,6067.6 ; U18.38@3766.2,5657.8 3766.2,5677.5 ; C9.1@4082.2,5411.5 4011.7,5482 4011.7,5580.8 4061.7,5630.8 U18.53@4061.7,5660.8 ; v1(4143.2,5733) 4143.2,5713 ; v1(4143.2,5863) 4143.2,5983 4125.5,6000.7 U18.71@4106.2,6000.7 4086.4,6000.7 4061.7,6025.4 U18.2@4061.7,6048.6 U18.3@4042,6048.6 4042,6028.8 4032,6018.8 3972,6018.8 3963.3,6027.5 U18.7@3963.3,6048.6 3963.3,6028.8 3953.3,6018.8 3813.3,6018.8 3805.8,6026.2 U18.15@3805.8,6048.6 3805.8,6068.4 3796.6,6077.6 3755.8,6077.6 v1@3745.8,6067.6 ; U7.8@4313.2,5627.1 4313.2,5653 4303.2,5663 4193.2,5663 4143.2,5713 ; 3766.2,5677.5 3776.2,5687.5 4051.7,5687.5 4061.7,5677.5 U18.53@4061.7,5657.6 U18.53@4061.7,5660.8 ; U18.53@4061.7,5660.8 4066.4,5665.5 4066.4,5685.5 4086.4,5705.5 U18.56@4106.2,5705.5 4135.7,5705.5 4143.2,5713
  Top Layer w8.5: U10.1@4696.5,4271.5 4716.5,4251.5 4856.5,4251.5 ; U14.22@4862.2,4267.1 4869.9,4267.1 U14.23@4879.1,4276.4 4879.1,4306.4 4895.7,4323 U14.3@4918.7,4323 4900.6,4323 4890.6,4333 4890.6,4381.2 ; U14.22@4862.2,4276.4 4862.2,4257.1 4856.5,4251.5 ; U14.8@4879.1,4386.6 4884.5,4381.2 4890.6,4381.2 ; U14.7@4896,4386.6 4890.6,4381.2 ; U14.1@4913,4276.4 U14.1@4916.5,4271.5 ; U11.3@5012.9,4421.4 5006.5,4414.9 5006.5,4351.5 4926.5,4271.5 U14.1@4916.5,4271.5 ; 4856.5,4251.5 4886.5,4221.5 4906.5,4221.5 4926.5,4241.5 4926.5,4251.5 4916.5,4261.5 U14.1@4916.5,4271.5
  Top Layer w8.9: U8.6@3647.7,5060.9 3697.7,5110.9 3817.8,5110.9 3940.6,4988 3940.6,4878 ; U15.11@3923.9,4848 3923.9,4861.3 3940.6,4878 ; U15.28@4002.6,4725 U15.28@4006.7,4720.9 ; R37.2@4128.7,4944.4 4052.3,4868 4040.6,4868 ; U9.6@4143.1,4574.6 4143.1,4620.9 4063.1,4700.9 4016.7,4700.9 4006.7,4710.9 U15.28@4006.7,4720.9 ; 3940.6,4878 4030.6,4878 4040.6,4868 ; U15.28@4006.7,4720.9 4006.7,4740.9 3996.7,4750.9 3996.7,4760.9 4012.4,4776.6 U15.3@4022.3,4776.6 U15.4@4022.3,4796.3 4032.3,4796.3 4052.3,4816.3 4052.3,4836.3 4040.6,4848 4040.6,4868
  Top Layer w9.9: U7.8@4313.2,5627.1 4318.2,5632.1 4480.4,5632.1 4570.4,5722.1 L2.2@4638.7,5722.1 ; U6.8@4527.7,4411.5 4546.9,4411.5 4626.9,4331.5 4626.9,4295.1 U10.6@4630.9,4291.1 4655,4291.1 4683.4,4262.8 ; U10.10@4683.4,4248.9 4683.4,4262.8 ; U10.1@4696.5,4271.5 4687.8,4262.8 4683.4,4262.8 ; C30.1@4885.8,4772.6 4915.2,4801.9 4915.2,4890.9 ; 4985.2,5030.9 4985.2,5040.9 5075.2,5130.9 5075.2,4926.6 5085.2,4916.6 5115.2,4916.6 5125.2,4926.6 5125.2,4956.6 5132.2,4963.6 C8.1@5132.2,5069.5 ; U13.5@5039.3,4841.3 U13.6@5039.3,4821.7 5031.8,4821.7 5024.4,4814.2 5024.4,4777 5034.4,4767 5084.4,4767 5103.2,4785.8 U13.10@5103.2,4797
  Top Layer w10: U9.6@4143.1,4574.6 4223.5,4654.9 4398.7,4654.9 4469.1,4584.5 C27.1@4575.8,4584.5 4590.2,4570.1 4610.8,4570.1 ; U6.8@4527.7,4411.5 4636.3,4520.1 4640.8,4520.1 C32.1@4640.7,4530 ; L2.2@4638.7,5722.1 4737,5722.1 4767,5752.1 5070.1,5752.1 C31.1@5101.1,5783.1 ; C26.1@4730.8,4510 4650.8,4510 4610.8,4550.1 4610.8,4570.1 ; C30.1@4885.8,4772.6 4845.8,4772.6 4745.9,4672.6 4745.9,4655.2 C33.1@4743.7,4653 4733.7,4653 4670.8,4590.1 4630.8,4590.1 4610.8,4570.1 ; 4926.5,4241.5 4975.8,4241.5 R39.2@5073.7,4143.5 R6.2@5138.7,4143.5 5258.7,4143.5 5356.7,4045.5 U12.18@5373.7,4045.5 5373.7,3889.1 5533.7,3729.1 5582.1,3729.1 5622.1,3689.1 5622.1,3669.1 U12.6@5623.7,3667.5 5623.7,3631.2 5533.7,3541.2 5533.7,3531.2 5503.7,3501.2 5473.7,3501.2 5403.7,3431.2 5273.7,3431.2 5238.4,3466.5 5158.4,3466.5 5132.2,3492.7 C16.1@5132.2,3496.5 ; 5006.5,4351.5 5036.5,4351.5 R36.2@5069.5,4318.5 ; U11.3@5012.9,4421.4 U11.2@5044.5,4421.4 U11.7@5044.5,4531.6 ; R17.2@5050.1,5179.9 5075.2,5154.9 5075.2,5130.9 ; R36.2@5073.8,4318.5 R36.2@5069.5,4318.5 ; 5132.2,5033.6 v1(5152.2,5033.6) ; R38.2@5138.8,4318.5 R36.2@5069.5,4318.5 ; C28.1@5356.1,5828.2 5356.1,5835.9 5372.2,5852 5642.2,5852 5762.2,5732 5762.2,5173.6 5682.2,5093.6 5522.2,5093.6 v1(5512.2,5083.6) 5512.2,4994.4 U2.1@5507.4,4989.6 5597.4,4899.6 5597.4,4682.6 5660.2,4619.8 U17.1@5670.2,4619.8 5670.2,4465.4 R2.1@5751.8,4383.9 ; 5672.2,5822 5672.2,5960 H1.13@5713.7,6001.5 ; U31.3@5713.7,5616.5 5718.2,5612 5762.2,5612 ; 5762.2,5552 5802.2,5592 5978.2,5592 U20.3@6023.7,5546.5
  Inner1 w7.8: v1(4495.5,4982.1) 4525.5,5012.1 4525.5,5062.1 4665.5,5202.1 4715.5,5202.1 4755.5,5242.1 4755.5,5292.1 v1(4785.5,5322.1)
  Inner1 w10: v1(5152.2,5033.6) 5332.2,5213.6 5372.2,5213.6 5502.2,5083.6 v1(5512.2,5083.6)
  Inner2 w8.1: v1(3695.8,6047.6) 3725.8,6077.6 v1(3745.8,6077.6) ; v1(4143.2,5733) v1(4143.2,5863)
$1N340: U3.2 U3.3 U3.8 U3.9 USBC1.A4B9 | length 2987.2
  Top Layer w7.1: USBC1.A4B9@4753.2,6164.1 4753.2,6122.8 v1(4766.2,6109.7) ; U3.2@5280.5,4169.7 U3.3@5296.2,4169.7 5296.2,4205.1 v1(5306.2,4215.1) ; v1(5336.2,4109.7) 5426.2,4109.7 5446.2,4129.7 5446.2,4159.7 5421.2,4184.7 5411.2,4184.7 5396.2,4169.7 U3.8@5375,4169.7 ; 5400.5,4175.6 5406.2,4179.7
  Inner2 w7.1: v1(4766.2,6109.7) 4856.2,6019.7 4856.2,5999.7 4896.2,5959.7 4926.2,5959.7 5276.2,5609.7 5276.2,5329.7 5406.2,5199.7 5406.2,4799.7 5356.2,4749.7 5356.2,4329.7 5393.2,4292.7 5393.2,4156.7 5346.2,4109.7 v1(5336.2,4109.7)
  Bottom Layer w7.1: v1(5306.2,4215.1) 5306.2,4199.7 5256.2,4149.7 5246.2,4149.7 5226.2,4129.7 5226.2,4109.7 5246.2,4089.7 5256.2,4089.7 5276.2,4109.7 v1(5336.2,4109.7)
$1N342: U1.49 U12.8 | length 2171.3
  Top Layer w7.8: U1.49@4652.3,5284.7 4652.3,5261.7 v1(4662.3,5251.7) ; v1(5592.3,3821.7) 5723.7,3690.3 U12.8@5723.7,3667.5
  Inner2 w7.8: v1(4662.3,5251.7) 4682.3,5271.7 4732.3,5271.7 5032.3,4971.7 5102.3,4971.7 5232.3,4841.7 5232.3,4341.7 5282.3,4291.7 5282.3,4131.7 v1(5592.3,3821.7)
$1N343: R11.1 U12.10 | length 863.8
  Top Layer w10: R11.1@5131.7,3636.5 5131.7,3625.9 5151.1,3606.5 5191.1,3606.5 v1(5201.1,3616.5) ; v1(5613.7,3849.1) 5773.7,4009.1 U12.10@5773.7,4045.5
  Bottom Layer w10: v1(5201.1,3616.5) 5223.7,3639.1 5323.7,3639.1 5533.7,3849.1 v1(5613.7,3849.1)
$1N345: Q1.1 R11.2 R14.1 | length 423.6
  Top Layer w10: v1(5126,3736.6) 5126,3765.9 R14.1@5126.7,3766.5 ; R11.2@5165.7,3636.5 5175.9,3646.6 5206,3646.6 5350.7,3501.9 Q1.1@5350.7,3476.6
  Inner2 w10: v1(5126,3736.6) 5196,3666.6 v1(5196,3646.6)
$1N347: Q1.3 R16.1 U21.2 | length 788.2
  Top Layer w10: R16.1@5026.7,3763.9 4997.3,3734.5 4997.3,3694 5007.3,3684 5037.3,3684 5137.3,3584 5202,3584 Q1.3@5272,3514 ; v1(5067.3,3634) 5077.3,3644
  Inner2 w10: U21.2@4851.6,3436.8 4947.5,3436.8 5067.3,3556.7 v1(5067.3,3634)
$1N348: D2.1 R15.1 R16.2 U12.12 | length 1396.8
  Top Layer w10: D2.1@5034.3,3331.5 5071.3,3368.5 5071.3,3521.5 5111.3,3561.5 ; R16.2@5060.8,3763.9 5066,3769.1 5073.7,3769.1 ; v1(5093.7,3769.1) 5073.7,3769.1 ; R15.1@5131.7,3561.5 5111.3,3561.5 ; v1(5463.7,3839.1) 5483.7,3839.1 5673.7,4029.1 U12.12@5673.7,4045.5 ; 5073.7,3769.1 5053.7,3789.1 5013.7,3789.1 4973.7,3749.1 4973.7,3689.1 5053.7,3609.1 5063.7,3609.1 5111.3,3561.5
  Inner2 w10: v1(5093.7,3769.1) 5393.7,3769.1 v1(5463.7,3839.1)
$1N349: D1.1 R18.2 R19.1 U12.13 | length 1352.7
  Top Layer w10: v1(5039.7,3565.5) 5039.7,3431.9 D1.1@5039.3,3431.5 4999.3,3391.5 4999.3,3306.5 5009.3,3296.5 5059.3,3296.5 5139.3,3376.5 R19.1@5211.7,3376.5 ; R18.2@5165.7,3701.5 5179.7,3715.5 v1(5189.7,3715.5) ; v1(5433.7,3865.5) 5463.7,3865.5 5623.7,4025.5 U12.13@5623.7,4045.5
  Inner1 w10: v1(5039.7,3565.5) v1(5189.7,3715.5)
  Bottom Layer w10: v1(5189.7,3715.5) 5189.7,3720.5 5194.7,3725.5 5293.7,3725.5 v1(5433.7,3865.5)
$1N350: R13.1 U12.11 | length 890.3
  Top Layer w10: R13.1@5026.7,3706.5 5026.7,3712.1 5043.7,3729.1 5083.7,3729.1 5093.7,3719.1 v1(5093.7,3709.1) ; v1(5513.7,3789.1) 5723.7,3999.1 U12.11@5723.7,4045.5
  Inner1 w10: v1(5093.7,3709.1) 5143.7,3709.1 5223.7,3789.1 v1(5513.7,3789.1)
$1N351: Q2.1 R13.2 R20.1 | length 691.2
  Top Layer w10: R13.2@5060.7,3706.5 5088.1,3679.1 v1(5103.4,3679.1) ; v1(5463.4,3449.1) 5483.4,3469.1 Q2.1@5498.1,3469.1 5499.3,3469.1 R20.1@5596.7,3566.5
  Inner2 w10: v1(5103.4,3679.1) 5333.4,3449.1 v1(5463.4,3449.1)
$1N352: Q2.3 R18.1 U33.2 | length 1344.5
  Top Layer w10: R18.1@5131.7,3701.5 5131.7,3691.5 5151.7,3671.5 5189.6,3671.5 v1(5214.6,3696.5) ; v1(5394.6,3556.5) 5419.3,3531.8 Q2.3@5419.3,3506.5
  Inner1 w10: U33.2@4382,3442.4 4442,3502.4 4909.5,3502.4 ; 4912.6,3502.4 5010.5,3502.4 5204.6,3696.5 v1(5214.6,3696.5) 5254.6,3696.5 v1(5394.6,3556.5)
$1N353: R38.1 U1.13 U3.15 U8.4 U9.4 U12.2 U18.30 | length 5026.7
  Top Layer w7.1: v1(5380.8,3845.9) 5423.7,3803 U12.2@5423.7,3667.5 ; U3.15@5402.5,4285.9 5420.8,4285.9 5430.8,4295.9 v1(5430.8,4325.9)
  Top Layer w7.8: U9.4@4123.4,4408.4 4123.4,4318.4 4203.4,4238.4 4347.3,4238.4 4367.3,4258.4 4367.3,4304.9 4384.2,4288.1 cw(c4372.2,4276.1) v1@4389.2,4276.1 ; v1(5003.4,4278.4) 5023.4,4258.4 5112.8,4258.4 R38.1@5138.8,4284.4
  Top Layer w8.1: v1(3693.4,5805.3) 3720.5,5805.3 U18.30@3721.9,5803.9
  Top Layer w10: U8.4@3813.9,5041.2 3847.5,5041.2 3863.4,5025.3 v1(3863.4,4955.3) ; U9.4@4123.4,4408.4 4123.4,4455.3 v1(4133.4,4465.3) ; U1.13@4668.5,4889.5 4668.5,4885.2 ccw(c4679.5,4885.2) 4669.09,4881.64 ; v1@4669.1,4831.4 4669.1,4881.6
  Inner1 w7.1: v1(5003.4,4278.4) 5196,4085.9 5350.8,4085.9 ; v1(5380.8,3845.9) 5350.8,3875.9 5350.8,4085.9 ; v1(5430.8,4325.9) 5440.8,4315.9 5440.8,4145.9 5380.8,4085.9 5350.8,4085.9
  Inner1 w7.8: v1@4391,4272.7 4408.4,4272.7 ; 4408.9,4272.9 4483.4,4198.4 4913.4,4198.4 4993.4,4278.4 v1(5003.4,4278.4)
  Inner1 w8.1: v1(3693.4,5805.3) 3683.4,5795.3 3683.4,5135.3 v1(3863.4,4955.3)
  Inner1 w10: v1(3863.4,4955.3) 3833.4,4925.3 3833.4,4765.3 v1(4133.4,4465.3) ; v1@4390.4,4272.1 4391,4272.7 4498.3,4380 ccw(c4427.6,4450.7) 4527.6,4450.7 v1@4527.6,4508.9
  Inner2 w10: v1@4535.7,4708.4 4652.4,4825.1 ; 4652.46,4825.14 cw(c4667.8,4809.8) v1@4667.8,4831.5
  Bottom Layer w10: v1@4532.5,4511.3 4532.5,4703.2 cw(c4541.6,4703.2) v1@4535.17,4709.63
  other v1: 4390.2,4273.1 4528.2,4510.7 4536.4,4709.5 4669,4831.5
$1N356: C11.1 C12.1 C13.1 C14.1 L1.2 U1.10 U1.32 U1.51 U1.59 U1.65 | length 3934.5
  Top Layer w7.8: L1.2@4303.7,5876.7 4349.3,5876.7 4409.3,5816.7 4409.3,5706.7 v1(4359.3,5656.7) ; v1(4369.3,5556.7) 4359.3,5546.7 4359.3,5216.7 4397.9,5178.1 U1.65@4435.5,5178.1 ; 4389.3,5186.7 4399.3,5176.7 4489.3,5176.7 4519.3,5146.7 4519.3,5136.7 4549.3,5106.7 4549.3,5016.7 4619.3,4946.7 4619.3,4916.7 ; 4409.3,5726.7 4489.3,5726.7 4589.3,5826.7 4809.3,5826.7 4848,5788 C14.1@5006.1,5788 ; U1.59@4494.8,5284.7 4494.8,5421.1 v1(4534.8,5461.1) ; 4494.8,5391.1 4564.8,5391.1 4620.8,5335.2 U1.51@4620.8,5284.7 ; v1(4583.5,4976.7) 4593.5,4976.7 4619.3,4950.8 4619.3,4916.7 ; U1.10@4620.8,4898.3 4619.3,4899.8 4619.3,4916.7 ; U1.32@4821.9,5115.1 4875,5115.1 4981.9,5008.2 v1(4981.9,4968.2)
  Top Layer w10: 4978,5788 4978,5868 4988,5878 5058,5878 5088,5848 C11.1@5098,5848 ; C11.1@5101.1,5848.1 C11.1@5098,5848 ; v1(5148,5878) 5128,5878 C11.1@5098,5848 ; v1(5261.1,5791.1) C13.1@5261.1,5768 5261.1,5763.1 5281.1,5743.1 5336.1,5743.1 C12.1@5356.1,5763.1
  Inner1 w7.8: v1(4359.3,5656.7) 4359.3,5636.7 v1(4534.8,5461.1)
  Inner2 w7.8: v1(4359.3,5656.7) 4359.3,5566.7 v1(4369.3,5556.7)
  Inner2 w10: v1(5148,5878) 5174.2,5878 v1(5261.1,5791.1)
  Bottom Layer w7.8: v1(4583.5,4976.7) 4593.5,4966.7 4613.5,4966.7 4653.5,5006.7 4813.5,5006.7 4831.9,4988.2 4961.9,4988.2 v1(4981.9,4968.2)
pads on no net: CARD1.3 CARD1.4 CARD1.6 CARD1.8 U2.8 U4.5 U5.5 U10.7 U12.7 U12.14 U12.15 U12.16 U12.17 U13.7 U13.8 U14.6 U14.9 U14.10 U14.12 U14.13 U15.1 U15.5 U15.6 U15.7 U15.8 U15.12 U15.13 U15.21 U15.22 U15.23 U15.24 U15.26 U15.27 U16.2 U16.4 U18.4 U18.5 U18.8 U18.9 U18.10 U18.11 U18.12 U18.13 U18.23 U18.26 U18.27 U18.28 U18.29 U18.39 U18.40 U18.41 U18.42 U18.43 U18.44 U18.45 U18.46 U18.47 U18.48 U18.49 U18.50 U18.51 U18.52 U18.60 U18.61 U18.62 U18.63 U18.64 U18.65 U18.66 U18.67 U18.68 U18.69 U18.70 U18.72 U22.2 U22.4 USBC1.1 USBC1.2 USBC1.3 USBC1.4 USBC1.A8 USBC1.B4A9 USBC1.B6 USBC1.B7 USBC1.B8 X2.1 X2.3

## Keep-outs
Board Outline Layer:
  lines w10: 3000,4771.7 3000.4,4734 3001.6,4696.5 3003.6,4658.9 3006.4,4621.4 3010,4584 3014.3,4546.6 3019.5,4509.4 3025.5,4472.2 3032.2,4435.2 3039.8,4398.4 3048.1,4361.7 3057.2,4325.2 3067,4288.9 3077.7,4252.9 3089.1,4217 3101.2,4181.4 3114.1,4146.1 3127.8,4111.1 3142.1,4076.3 3157.3,4041.9 3173.1,4007.8 3189.7,3974 3207,3940.7 3225,3907.6 3243.7,3875 3263,3842.8 3283.1,3811 3303.8,3779.6 3325.2,3748.6 3347.2,3718.2 3369.9,3688.2 3393.2,3658.7 3417.2,3629.7 3441.7,3601.2 3466.9,3573.2 3492.6,3545.8 3518.9,3518.9 3545.8,3492.6 3573.2,3466.9 3601.2,3441.7 3629.7,3417.2 3658.7,3393.2 3688.2,3369.9 3718.2,3347.2 3748.6,3325.2 3779.6,3303.8 3811,3283.1 3842.8,3263 3875,3243.7 3907.6,3225 3940.7,3207 3974,3189.7 4007.8,3173.1 4041.9,3157.3 4076.3,3142.1 4111.1,3127.8 4146.1,3114.1 4181.4,3101.2 4217,3089.1 4252.9,3077.7 4288.9,3067 4325.2,3057.2 4361.7,3048.1 4398.4,3039.8 4435.2,3032.2 4472.2,3025.5 4509.4,3019.5 4546.6,3014.3 4584,3010 4621.4,3006.4 4658.9,3003.6 4696.5,3001.6 4734,3000.4 4771.7,3000 4809.3,3000.4 4846.8,3001.6 4884.4,3003.6 4921.9,3006.4 4959.3,3010 4996.7,3014.3 5033.9,3019.5 5071.1,3025.5 5108.1,3032.2 5144.9,3039.8 5181.6,3048.1 5218.1,3057.2 5254.4,3067 5290.4,3077.7 5326.3,3089.1 5361.9,3101.2 5397.2,3114.1 5432.2,3127.8 5467,3142.1 5501.4,3157.3 5535.5,3173.1 5569.3,3189.7 5602.7,3207 5635.7,3225 5668.3,3243.7 5700.5,3263 5732.4,3283.1 5763.7,3303.8 5794.7,3325.2 5825.1,3347.2 5855.1,3369.9 5884.6,3393.2 5913.6,3417.2 5942.1,3441.7 5970.1,3466.9 5997.5,3492.6 6024.4,3518.9 6050.7,3545.8 6076.4,3573.2 6101.6,3601.2 6126.1,3629.7 6150.1,3658.7 6173.4,3688.2 6196.1,3718.2 6218.1,3748.6 6239.5,3779.6 6260.2,3811 6280.3,3842.8 6299.6,3875 6318.3,3907.6 6336.3,3940.7 6353.6,3974 6370.2,4007.8 6386,4041.9 6401.2,4076.3 6415.6,4111.1 6429.2,4146.1 6442.1,4181.4 6454.3,4217 6465.6,4252.9 6476.3,4288.9 6486.1,4325.2 6495.2,4361.7 6503.5,4398.4 6511.1,4435.2 6517.8,4472.2 6523.8,4509.4 6529,4546.6 6533.3,4584 6536.9,4621.4 6539.7,4658.9 6541.7,4696.5 6542.9,4734 6543.3,4771.7 6542.9,4809.3 6541.7,4846.8 6539.7,4884.4 6536.9,4921.9 6533.3,4959.3 6529,4996.7 6523.8,5033.9 6517.8,5071.1 6511.1,5108.1 6503.5,5144.9 6495.2,5181.6 6486.1,5218.1 6476.3,5254.4 6465.6,5290.4 6454.3,5326.3 6442.1,5361.9 6429.2,5397.2 6415.6,5432.2 6401.2,5467 6386,5501.4 6370.2,5535.5 6353.6,5569.3 6336.3,5602.7 6318.3,5635.7 6299.6,5668.3 6280.3,5700.5 6260.2,5732.4 6239.5,5763.7 6218.1,5794.7 6196.1,5825.1 6173.4,5855.1 6150.1,5884.6 6126.1,5913.6 6101.6,5942.1 6076.4,5970.1 6050.7,5997.5 6024.4,6024.4 5997.5,6050.7 5970.1,6076.4 5942.1,6101.6 5913.6,6126.1 5884.6,6150.1 5855.1,6173.4 5825.1,6196.1 5794.7,6218.1 5763.7,6239.5 5732.4,6260.2 5700.5,6280.3 5668.3,6299.6 5635.7,6318.3 5602.7,6336.3 5569.3,6353.6 5535.5,6370.2 5501.4,6386 5467,6401.2 5432.2,6415.6 5397.2,6429.2 5361.9,6442.1 5326.3,6454.3 5290.4,6465.6 5254.4,6476.3 5218.1,6486.1 5181.6,6495.2 5144.9,6503.5 5108.1,6511.1 5071.1,6517.8 5033.9,6523.8 4996.7,6529 4959.3,6533.3 4921.9,6536.9 4884.4,6539.7 4846.8,6541.7 4809.3,6542.9 4771.7,6543.3 4734,6542.9 4696.5,6541.7 4658.9,6539.7 4621.4,6536.9 4584,6533.3 4546.6,6529 4509.4,6523.8 4472.2,6517.8 4435.2,6511.1 4398.4,6503.5 4361.7,6495.2 4325.2,6486.1 4288.9,6476.3 4252.9,6465.6 4217,6454.3 4181.4,6442.1 4146.1,6429.2 4111.1,6415.6 4076.3,6401.2 4041.9,6386 4007.8,6370.2 3974,6353.6 3940.7,6336.3 3907.6,6318.3 3875,6299.6 3842.8,6280.3 3811,6260.2 3779.6,6239.5 3748.6,6218.1 3718.2,6196.1 3688.2,6173.4 3658.7,6150.1 3629.7,6126.1 3601.2,6101.6 3573.2,6076.4 3545.8,6050.7 3518.9,6024.4 3492.6,5997.5 3466.9,5970.1 3441.7,5942.1 3417.2,5913.6 3393.2,5884.6 3369.9,5855.1 3347.2,5825.1 3325.2,5794.7 3303.8,5763.7 3283.1,5732.4 3263,5700.5 3243.7,5668.3 3225,5635.7 3207,5602.7 3189.7,5569.3 3173.1,5535.5 3157.3,5501.4 3142.1,5467 3127.8,5432.2 3114.1,5397.2 3101.2,5361.9 3089.1,5326.3 3077.7,5290.4 3067,5254.4 3057.2,5218.1 3048.1,5181.6 3039.8,5144.9 3032.2,5108.1 3025.5,5071.1 3019.5,5033.9 3014.3,4996.7 3010,4959.3 3006.4,4921.9 3003.6,4884.4 3001.6,4846.8 3000.4,4809.3 3000,4771.7

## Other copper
Top Layer:
  text "Brake Header" at 3123.7,5046.5 h39.4
  text "Ejection Ports" at 3833.7,3316.5 h39.4
  text "WYVERN-E" at 4411.5,3055.2 h120
Bottom Layer:
  text "TVC Header" at 5186.3,3836.5 h39.4
  text "Fin Header" at 3568.7,3746.5 h39.4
